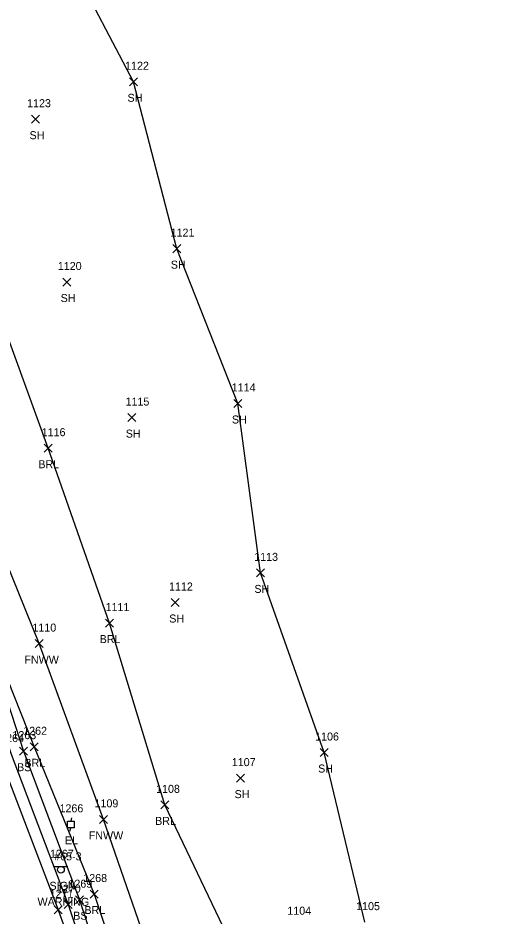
# Model space of a CAD drawing. Extents: x 1443590 to 1445966, y 578314 to 580556.
# Drawn here: x 1445349.1 to 1445467.8, y 578567.5 to 578791.8 of the extents above; entities that cross this region are included whole.
import ezdxf

# ---------------------------------------------------------------- set-up
doc = ezdxf.new("R2010")
doc.units = 0
for name, color, linetype in [('L_A', 7, 'Continuous'), ('L_I', 7, 'Continuous'), ('L_TIC', 7, 'Continuous'), ('LABL', 7, 'Continuous'), ('LELB', 7, 'Continuous'), ('LFNC', 7, 'Continuous'), ('LSOGP', 7, 'Continuous'), ('P_I', 7, 'Continuous'), ('P_TIC', 7, 'Continuous'), ('PET', 7, 'Continuous'), ('S_A', 7, 'Continuous'), ('S_C', 7, 'Continuous'), ('S_I', 7, 'Continuous'), ('SSGN', 7, 'Continuous'), ('U_A', 7, 'Continuous'), ('U_C', 7, 'Continuous'), ('U_I', 7, 'Continuous'), ('UEPT', 7, 'Continuous')]:
    doc.layers.add(name, color=color, linetype=linetype)

msp = doc.modelspace()

# ---------------------------------------------------------------- linework, layer by layer
at = {"layer": 'L_TIC'}
for points in [[(1445377, 578774.88), (1445379, 578776.88)], [(1445379, 578774.88), (1445377, 578776.88)], [(1445352.52, 578765.53), (1445354.52, 578767.53)], [(1445354.52, 578765.53), (1445352.52, 578767.53)], [(1445387.82, 578733.19), (1445389.82, 578735.19)], [(1445389.82, 578733.19), (1445387.82, 578735.19)], [(1445360.28, 578724.86), (1445362.28, 578726.86)], [(1445362.28, 578724.86), (1445360.28, 578726.86)], [(1445403.09, 578694.52), (1445405.09, 578696.52)], [(1445405.09, 578694.52), (1445403.09, 578696.52)], [(1445376.55, 578691), (1445378.55, 578693)], [(1445378.55, 578691), (1445376.55, 578693)], [(1445355.66, 578683.35), (1445357.66, 578685.35)], [(1445357.66, 578683.35), (1445355.66, 578685.35)], [(1445408.71, 578652.21), (1445410.71, 578654.21)], [(1445410.71, 578652.21), (1445408.71, 578654.21)], [(1445387.42, 578644.81), (1445389.42, 578646.81)], [(1445389.42, 578644.81), (1445387.42, 578646.81)], [(1445370.99, 578639.68), (1445372.99, 578641.68)], [(1445372.99, 578639.68), (1445370.99, 578641.68)], [(1445353.37, 578634.55), (1445355.37, 578636.55)], [(1445355.37, 578634.55), (1445353.37, 578636.55)], [(1445349.45, 578607.68), (1445351.45, 578609.68)], [(1445351.45, 578607.68), (1445349.45, 578609.68)], [(1445352.16, 578608.77), (1445354.16, 578610.77)], [(1445354.16, 578608.77), (1445352.16, 578610.77)], [(1445424.64, 578607.34), (1445426.64, 578609.34)], [(1445426.64, 578607.34), (1445424.64, 578609.34)], [(1445403.76, 578600.95), (1445405.76, 578602.95)], [(1445405.76, 578600.95), (1445403.76, 578602.95)], [(1445384.83, 578594.27), (1445386.83, 578596.27)], [(1445386.83, 578594.27), (1445384.83, 578596.27)], [(1445369.45, 578590.65), (1445371.45, 578592.65)], [(1445371.45, 578590.65), (1445369.45, 578592.65)], [(1445367.17, 578572), (1445369.17, 578574)], [(1445369.17, 578572), (1445367.17, 578574)], [(1445360.62, 578569.36), (1445362.62, 578571.36)], [(1445362.62, 578569.36), (1445360.62, 578571.36)], [(1445363.47, 578570.58), (1445365.47, 578572.58)], [(1445365.47, 578570.58), (1445363.47, 578572.58)]]:
    msp.add_lwpolyline(points, dxfattribs=at)
at = {"layer": 'LABL'}
for points in [[(1445467.84, 578360.06), (1445455.38, 578392.07), (1445446.82, 578428.87), (1445442.38, 578441.48), (1445436.55, 578457.59), (1445425.34, 578488.87), (1445418.21, 578516.65), (1445402.21, 578560.94), (1445385.83, 578595.27), (1445371.99, 578640.68), (1445356.66, 578684.35), (1445342.86, 578722.22), (1445331.82, 578758.2), (1445312.95, 578811.34), (1445309.58, 578818.49), (1445306.72, 578822.66), (1445303.45, 578826.18), (1445294.95, 578830.16), (1445285.99, 578855.57), (1445278.07, 578895.34), (1445273.01, 578922.07), (1445267.74, 578942.65), (1445247.28, 578957.13)], [(1445292.63, 578789.9), (1445288, 578780.72), (1445303.45, 578740.92), (1445320.45, 578696.23), (1445336.45, 578651.8), (1445353.16, 578609.77), (1445368.17, 578573), (1445383.72, 578526.34), (1445398.46, 578486.57), (1445412.31, 578451.09), (1445415.12, 578445.83), (1445420.11, 578428.88), (1445425.31, 578411.87), (1445435.24, 578381.31), (1445438.11, 578382.76), (1445447.54, 578352.71)]]:
    msp.add_lwpolyline(points, dxfattribs=at)
at = {"layer": 'LELB'}
for points in [[(1445222.69, 578937.93), (1445234.28, 578911.39), (1445254.78, 578861.13), (1445268.94, 578819.8), (1445281.41, 578785.26), (1445283.41, 578779.74), (1445299.6, 578739.58), (1445316.15, 578694.47), (1445332.79, 578650.27), (1445347.4, 578607.95), (1445361.62, 578570.36), (1445377.25, 578524), (1445391.22, 578483.59), (1445406.36, 578442.9), (1445418.34, 578410.04), (1445429.91, 578378.9), (1445440.4, 578350.18)], [(1445336.45, 578651.8), (1445350.45, 578608.68), (1445364.47, 578571.58), (1445379.66, 578524.91), (1445393.71, 578484.47), (1445409.17, 578449.94), (1445411.12, 578445.67), (1445411.54, 578444.09), (1445413.6, 578439.47), (1445415.72, 578428.29), (1445422.38, 578411.18), (1445431.91, 578379.51), (1445442.14, 578350.66)]]:
    msp.add_lwpolyline(points, dxfattribs=at)
at = {"layer": 'LFNC'}
msp.add_lwpolyline([(1445459.96, 578349.35), (1445445.8, 578387.44), (1445435.66, 578413.46), (1445430.43, 578428.44), (1445420.82, 578457.49), (1445411.95, 578480.76), (1445399.21, 578511.56), (1445382.81, 578556.03), (1445370.45, 578591.65), (1445354.37, 578635.55), (1445339.12, 578673.28), (1445323.48, 578719.9), (1445315.49, 578748.71)], dxfattribs=at)
at = {"layer": 'LSOGP'}
msp.add_lwpolyline([(1445435.83, 578565.97), (1445425.64, 578608.34), (1445409.71, 578653.21), (1445404.09, 578695.52), (1445388.82, 578734.18), (1445378, 578775.88), (1445362.42, 578805.61), (1445354.16, 578836.67), (1445344.42, 578860.17), (1445338.02, 578884.49), (1445332.44, 578895.48), (1445326.44, 578904.52), (1445322.58, 578909.3), (1445318.45, 578959.47), (1445320.47, 578993.49)], dxfattribs=at)
at = {"layer": 'P_TIC'}
for points in [[(1445358.16, 578568.06), (1445360.16, 578570.06)], [(1445360.16, 578568.06), (1445358.16, 578570.06)]]:
    msp.add_lwpolyline(points, dxfattribs=at)
at = {"layer": 'PET'}
msp.add_lwpolyline([(1445204.47, 578977.72), (1445211.07, 578960.69), (1445220.5, 578936.98), (1445230.76, 578910.15), (1445251.08, 578859.52), (1445265.4, 578819.79), (1445279.28, 578781.46), (1445295.62, 578738.27), (1445312.78, 578693.03), (1445329.09, 578649.05), (1445344.77, 578606.81), (1445359.16, 578569.06), (1445375.47, 578523.38), (1445389.92, 578483.27), (1445404.56, 578441.9), (1445416.57, 578409.56), (1445427.35, 578377.72), (1445437.94, 578349.1)], dxfattribs=at)
at = {"layer": 'SSGN'}
for p, q in [((1445358.2, 578579.91), (1445361.54, 578579.91)), ((1445359.85, 578579.08), (1445359.85, 578579.08))]:
    msp.add_line(p, q, dxfattribs=at)
msp.add_circle((1445359.85, 578579.08), 0.833, dxfattribs=at)
at = {"layer": 'UEPT'}
for p, q in [((1445361.45, 578589.56), (1445361.45, 578591.23)), ((1445361.45, 578591.23), (1445363.12, 578591.23)), ((1445362.45, 578592.06), (1445362.29, 578591.23)), ((1445363.12, 578591.23), (1445363.12, 578589.56)), ((1445363.12, 578589.56), (1445361.45, 578589.56)), ((1445362.04, 578588.73), (1445362.29, 578589.56)), ((1445362.29, 578590.4), (1445362.29, 578590.4))]:
    msp.add_line(p, q, dxfattribs=at)

# ---------------------------------------------------------------- texts
at = {"layer": 'L_A'}
for s, p in [('SH', (1445376.49, 578770.88)), ('SH', (1445352, 578761.53)), ('SH', (1445387.31, 578729.19)), ('SH', (1445359.77, 578720.86)), ('SH', (1445402.58, 578690.52)), ('SH', (1445376.04, 578687)), ('BRL', (1445354.2, 578679.35)), ('SH', (1445408.2, 578648.21)), ('SH', (1445386.91, 578640.81)), ('BRL', (1445369.53, 578635.68)), ('FNWW', (1445350.71, 578630.55)), ('BRL', (1445350.71, 578604.77)), ('BS', (1445348.89, 578603.68)), ('SH', (1445424.13, 578603.34)), ('SH', (1445403.24, 578596.95)), ('BRL', (1445383.38, 578590.27)), ('FNWW', (1445366.8, 578586.65)), ('BS', (1445362.91, 578566.58)), ('BRL', (1445365.71, 578568))]:
    msp.add_text(s, height=2, dxfattribs=at).set_placement(p)
at = {"layer": 'L_I'}
for s, p in [('1122', (1445375.88, 578778.88)), ('1123', (1445351.39, 578769.53)), ('1121', (1445387.26, 578737.19)), ('1120', (1445359.07, 578728.86)), ('1114', (1445402.53, 578698.52)), ('1115', (1445375.99, 578695)), ('1116', (1445355.04, 578687.35)), ('1113', (1445408.15, 578656.21)), ('1112', (1445386.86, 578648.81)), ('1111', (1445371, 578643.68)), ('1110', (1445352.72, 578638.55)), ('1263', (1445347.71, 578611.68)), ('1262', (1445350.42, 578612.77)), ('1264', (1445344.66, 578610.95)), ('1106', (1445423.38, 578611.34)), ('1107', (1445402.55, 578604.95)), ('1108', (1445383.63, 578598.27)), ('1109', (1445368.24, 578594.65)), ('1268', (1445365.43, 578576)), ('1270', (1445358.84, 578573.36)), ('1269', (1445361.72, 578574.58)), ('1105', (1445433.62, 578568.97)), ('1104', (1445416.43, 578567.83))]:
    msp.add_text(s, height=2, dxfattribs=at).set_placement(p)
at = {"layer": 'P_I'}
msp.add_text('1271', height=2, dxfattribs=at).set_placement((1445357.03, 578572.06))
at = {"layer": 'S_A'}
msp.add_text('SIGN', height=2, dxfattribs=at).set_placement((1445356.99, 578574.06))
at = {"layer": 'S_C'}
msp.add_text('WARNING', height=2, dxfattribs=at).set_placement((1445354, 578570.06))
at = {"layer": 'S_I'}
msp.add_text('1267', height=2, dxfattribs=at).set_placement((1445357.09, 578582.06))
at = {"layer": 'U_A'}
msp.add_text('EL', height=2, dxfattribs=at).set_placement((1445360.82, 578585.4))
at = {"layer": 'U_C'}
msp.add_text('#65-3', height=2, dxfattribs=at).set_placement((1445358.16, 578581.4))
at = {"layer": 'U_I'}
msp.add_text('1266', height=2, dxfattribs=at).set_placement((1445359.49, 578593.4))

doc.saveas('drawing.dxf')
